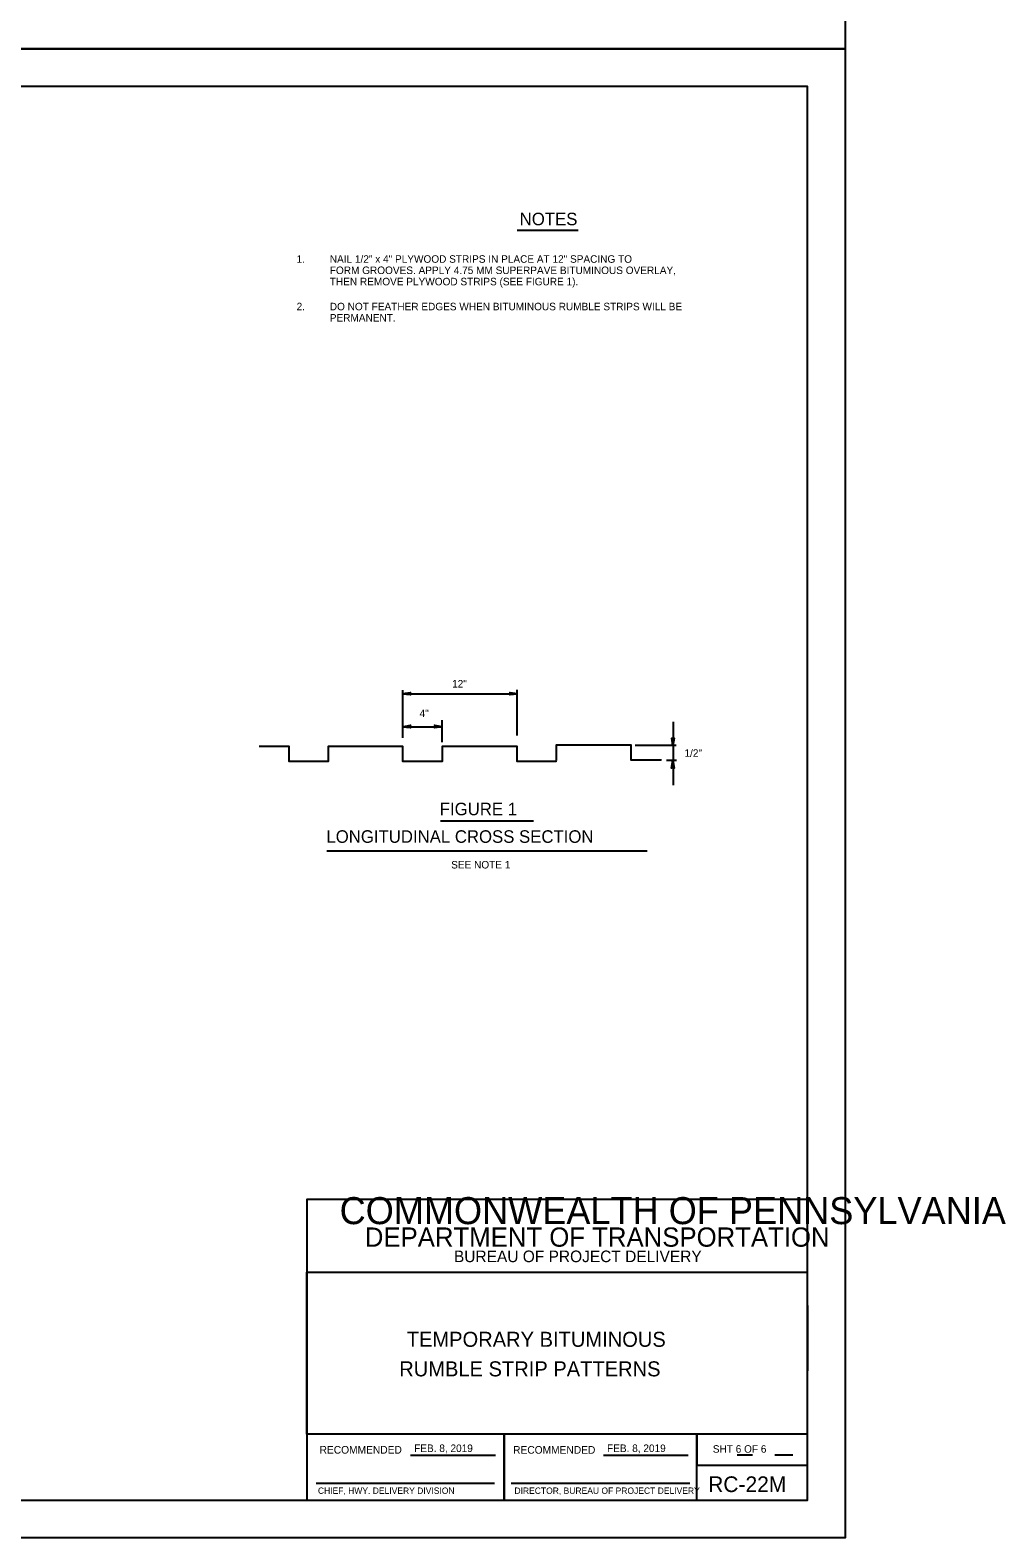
# Model space of a CAD drawing. Extents: x 632008 to 634206, y 294231 to 297795.
# Drawn here: x 632523 to 632913, y 294231 to 294832 of the extents above; entities that cross this region are included whole.
import ezdxf

# ---------------------------------------------------------------- set-up
doc = ezdxf.new("R2010")
doc.units = 0
for name, color, linetype in [('1', 7, 'Continuous'), ('Level 2', 7, 'Continuous'), ('Level 3', 7, 'Continuous'), ('PLT-BNDY', 7, 'Continuous')]:
    doc.layers.add(name, color=color, linetype=linetype)

msp = doc.modelspace()

# ---------------------------------------------------------------- linework, layer by layer
at = {"layer": '1'}
for p, q in [((632717.95, 294752.27), (632742.18, 294752.27)), ((632687.31, 294516.66), (632724.41, 294516.66)), ((632641.96, 294504.77), (632769.83, 294504.77)), ((632833.86, 294264.5), (632833.86, 294327.33)), ((632833.86, 294323.35), (632833.86, 294297.2)), ((632675.32, 294263.61), (632709.21, 294263.61)), ((632752.32, 294263.61), (632786.19, 294263.61)), ((632805.73, 294263.8), (632811.87, 294263.8)), ((632820.79, 294263.8), (632827.89, 294263.8)), ((632637.64, 294252.43), (632708.89, 294252.43)), ((632715.49, 294252.43), (632786.83, 294252.43))]:
    msp.add_line(p, q, dxfattribs=at)
msp.add_lwpolyline([(632833.86, 294245.62), (632833.86, 294809.62), (632047.86, 294809.62), (632047.86, 294245.62), (632833.86, 294245.62), (632833.86, 294271.98), (632633.86, 294271.98), (632633.86, 294336.66), (632833.86, 294336.66), (632833.86, 294365.62), (632633.86, 294365.62), (632633.86, 294245.62), (632712.66, 294245.62), (632712.66, 294271.98), (632712.66, 294245.62), (632789.66, 294245.62), (632789.66, 294271.98), (632789.66, 294259.66), (632833.86, 294259.66)], dxfattribs=at)
at = {"layer": 'Level 2'}
for p, q in [((632672.3, 294549.83), (632672.3, 294568.79)), ((632672.3, 294567.39), (632717.76, 294567.39)), ((632717.95, 294550.72), (632717.95, 294568.98)), ((632687.92, 294548.08), (632687.92, 294556.85)), ((632780.1, 294556.17), (632780.1, 294530.87)), ((632672.3, 294554.23), (632687.92, 294554.23)), ((632781.32, 294546.67), (632765, 294546.67)), ((632781.5, 294540.7), (632777.45, 294540.7))]:
    msp.add_line(p, q, dxfattribs=at)
for points in [[(632733.4, 294540.19), (632733.4, 294540.35), (632717.95, 294540.35), (632717.95, 294546.32), (632687.92, 294546.32), (632687.92, 294540.35), (632672.3, 294540.35), (632672.3, 294546.32), (632642.46, 294546.32), (632642.46, 294540.35), (632626.82, 294540.35), (632626.82, 294546.32), (632614.88, 294546.32)], [(632775.35, 294540.89), (632775.35, 294540.89), (632763.41, 294540.89), (632763.41, 294546.86), (632733.4, 294546.86), (632733.4, 294540.7)]]:
    msp.add_lwpolyline(points, dxfattribs=at)
at = {"layer": 'Level 3'}
for points in [[(632675.22, 294567.04), (632675.11, 294567.28), (632672.3, 294567.39), (632675.22, 294567.04), (632675.35, 294566.92), (632672.3, 294567.39), (632675.11, 294567.51), (632675.22, 294567.75), (632672.3, 294567.39), (632675.35, 294567.86), (632675.22, 294567.75)], [(632715.03, 294567.76), (632715.14, 294567.63), (632717.94, 294567.4), (632715.03, 294567.76), (632714.9, 294567.87), (632717.94, 294567.4), (632715.14, 294567.29), (632715.03, 294567.05), (632717.94, 294567.4), (632714.9, 294566.93), (632715.03, 294567.05)], [(632675.22, 294553.87), (632675.11, 294554.11), (632672.3, 294554.23), (632675.22, 294553.87), (632675.35, 294553.76), (632672.3, 294554.23), (632675.11, 294554.47), (632675.22, 294554.58), (632672.3, 294554.23), (632675.35, 294554.81), (632675.22, 294554.58)], [(632685, 294554.7), (632685.11, 294554.47), (632687.92, 294554.23), (632685, 294554.7), (632684.87, 294554.81), (632687.92, 294554.23), (632685.11, 294554.11), (632685, 294554), (632687.92, 294554.23), (632684.87, 294553.76), (632685, 294554)], [(632780.44, 294549.61), (632780.32, 294549.49), (632780.08, 294546.68), (632780.44, 294549.61), (632780.55, 294549.72), (632780.08, 294546.68), (632779.97, 294549.49), (632779.74, 294549.61), (632780.08, 294546.68), (632779.62, 294549.72), (632779.74, 294549.61)], [(632779.62, 294537.9), (632779.86, 294538.02), (632780.09, 294540.71), (632779.62, 294537.9), (632779.5, 294537.66), (632780.09, 294540.71), (632780.2, 294538.02), (632780.43, 294537.9), (632780.09, 294540.71), (632780.56, 294537.66), (632780.43, 294537.9)]]:
    msp.add_lwpolyline(points, dxfattribs=at)
at = {"layer": 'PLT-BNDY'}
for points in [[(632007.86, 295418.62), (632848.86, 295418.62), (632848.86, 294824.62), (632007.86, 294824.62)], [(632007.86, 294824.62), (632848.86, 294824.62), (632848.86, 294230.62), (632007.86, 294230.62)]]:
    msp.add_lwpolyline(points, close=True, dxfattribs=at)

# ---------------------------------------------------------------- texts
at = {"layer": '1'}
for s, height, p in [('NOTES', 5, (632718.9, 294754.29)), ('COMMONWEALTH OF PENNSYLVANIA', 10.7834, (632647.01, 294355.77)), ('DEPARTMENT OF TRANSPORTATION', 7.6843, (632657.07, 294346.77)), ('BUREAU OF PROJECT DELIVERY', 4.6221, (632692.65, 294340.61)), ('TEMPORARY BITUMINOUS', 6, (632673.8, 294306.83)), ('RUMBLE STRIP PATTERNS', 6, (632670.8, 294295.04)), ('RECOMMENDED', 3.048, (632639.02, 294264.22)), ('FEB. 8, 2019', 3, (632676.78, 294264.87)), ('RECOMMENDED', 3.048, (632716.27, 294264.19)), ('FEB. 8, 2019', 3, (632753.78, 294264.87)), ('SHT 6 OF 6', 3, (632795.99, 294264.58)), ('RC-22M', 6.267, (632794.14, 294248.88))]:
    msp.add_text(s, height=height, dxfattribs=at).set_placement(p)
for s, p in [('CHIEF, HWY. DELIVERY DIVISION', (632638.35, 294248.17)), ('DIRECTOR, BUREAU OF PROJECT DELIVERY', (632716.81, 294248.17))]:
    msp.add_text(s, height=2.54, rotation=360, dxfattribs=at).set_placement(p)
at = {"layer": 'Level 2'}
for s, height, p in [('1.', 3, (632629.84, 294739.32)), ('NAIL 1/2" x 4" PLYWOOD STRIPS IN PLACE AT 12" SPACING TO ', 3, (632643.09, 294739.32)), ('FORM GROOVES. APPLY 4.75 MM SUPERPAVE BITUMINOUS OVERLAY, ', 3, (632643.09, 294734.82)), ('THEN REMOVE PLYWOOD STRIPS (SEE FIGURE 1).', 3, (632643.09, 294730.32)), ('2.', 3, (632629.84, 294720.36)), ('DO NOT FEATHER EDGES WHEN BITUMINOUS RUMBLE STRIPS WILL BE ', 3, (632643.09, 294720.36)), ('PERMANENT.', 3, (632643.09, 294715.86)), ('12"', 3, (632691.91, 294569.86)), ('4"', 3, (632678.94, 294558.09)), ('1/2"', 3, (632784.68, 294542.22)), ('FIGURE 1', 5, (632687, 294518.91)), ('LONGITUDINAL CROSS SECTION', 5, (632641.74, 294507.91)), ('SEE NOTE 1', 3, (632691.55, 294497.67))]:
    msp.add_text(s, height=height, dxfattribs=at).set_placement(p)

doc.saveas('drawing.dxf')
